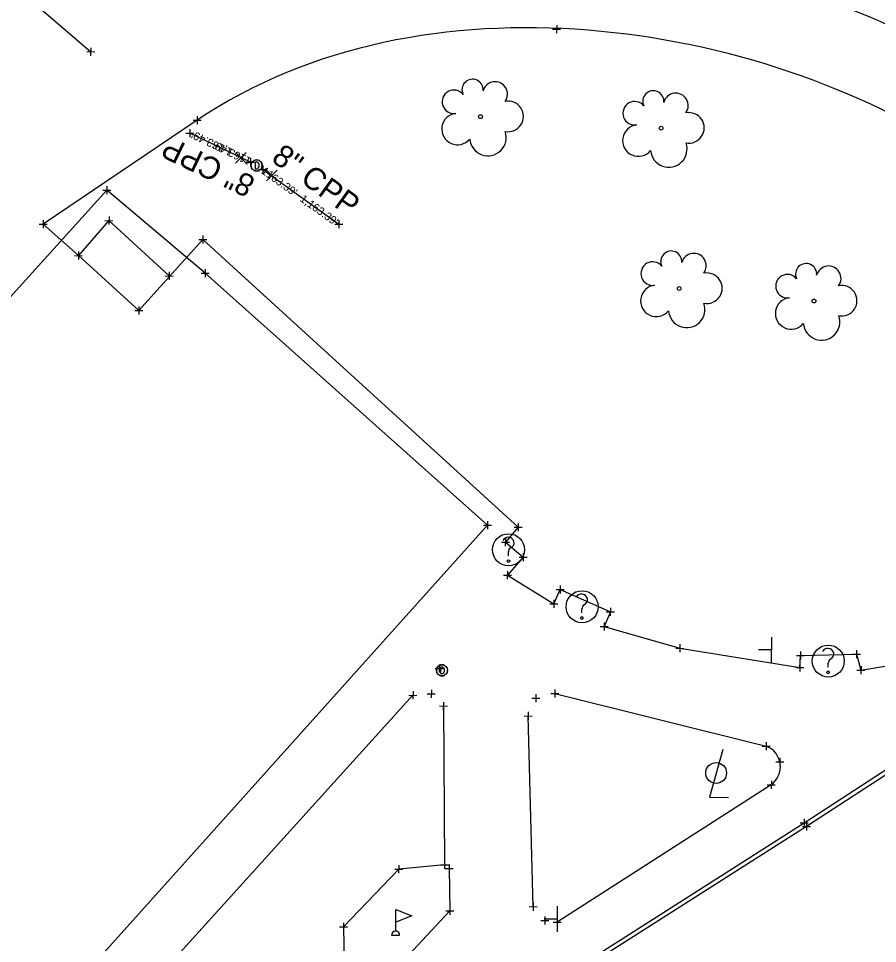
# Model space of a CAD drawing. Extents: x 142461 to 147261, y 511126 to 514697.
# Drawn here: x 145405.1 to 145512.4, y 513850.3 to 513965.9 of the extents above; entities that cross this region are included whole.
import ezdxf

# ---------------------------------------------------------------- set-up
doc = ezdxf.new("R2010")
doc.units = 0
for name, color, linetype in [('BD_X_Building', 7, 'Continuous'), ('DR_X_Cells', 7, 'Continuous'), ('DR_X_Elev_Flow', 7, 'Continuous'), ('DR_X_Storm_Sewer', 7, 'Continuous'), ('DR_X_Text', 7, 'Continuous'), ('GK_Drainage_Nodes', 7, 'Continuous'), ('LT_X_Poles', 7, 'Continuous'), ('PV_X_Curb', 7, 'Continuous'), ('PV_X_EOP', 7, 'Continuous'), ('PV_X_Walk', 7, 'Continuous'), ('RD_X_Cells', 7, 'Continuous'), ('RD_X_Misc_Items', 7, 'Continuous'), ('SC_Scratch1', 7, 'Continuous'), ('SN_X_Public', 7, 'Continuous'), ('SV_X_Random_Point', 7, 'Continuous'), ('SV_X_Shot_Marker', 7, 'Continuous'), ('VG_X_Cells', 7, 'Continuous')]:
    doc.layers.add(name, color=color, linetype=linetype)

msp = doc.modelspace()

# ---------------------------------------------------------------- linework, layer by layer
at = {"layer": 'BD_X_Building'}
msp.add_lwpolyline([(145428.41, 513934.11), (145416.13, 513944.48), (145358.84, 513881.1), (145404.83, 513837.03), (145463.67, 513902.61)], close=True, dxfattribs=at)
at = {"layer": 'DR_X_Cells'}
for points in [[(145434.92, 513947.97), (145434.64, 513947.97), (145434.64, 513947.17), (145434.92, 513947.17)], [(145458.07, 513884.88), (145457.79, 513884.88), (145457.79, 513884.08), (145458.07, 513884.08)]]:
    msp.add_lwpolyline(points, dxfattribs=at)
for centre, radius, start, end in [((145434.82, 513947.57), 0.7, 150.0184, 209.9816), ((145434.82, 513947.57), 0.7, 60.0184, 120.0157), ((145434.67, 513947.57), 0.474, 302.5148, 57.4852), ((145434.82, 513947.57), 0.7, 330.0184, 29.9816), ((145434.82, 513947.57), 0.7, 239.9843, 299.9816), ((145457.97, 513884.48), 0.7, 60.0184, 120.0157), ((145457.97, 513884.48), 0.7, 150.0184, 209.9816), ((145457.97, 513884.48), 0.7, 239.9843, 299.9816), ((145457.82, 513884.47), 0.474, 302.5148, 57.4852), ((145457.97, 513884.48), 0.7, 330.0184, 29.9816)]:
    msp.add_arc(centre, radius, start, end, dxfattribs=at)
at = {"layer": 'DR_X_Elev_Flow'}
for p, q in [((145426.49, 513952.12), (145426.49, 513951.12)), ((145425.99, 513951.62), (145426.99, 513951.62)), ((145426.49, 513951.62), (145426.49, 513951.62)), ((145434.05, 513948.49), (145434.05, 513947.49)), ((145433.55, 513947.99), (145434.55, 513947.99)), ((145434.05, 513947.99), (145434.05, 513947.99)), ((145435.61, 513947.58), (145435.61, 513946.58)), ((145435.11, 513947.08), (145436.11, 513947.08)), ((145435.61, 513947.08), (145435.61, 513947.08)), ((145445.11, 513940.72), (145445.11, 513939.72)), ((145444.61, 513940.22), (145445.61, 513940.22)), ((145445.11, 513940.22), (145445.11, 513940.22))]:
    msp.add_line(p, q, dxfattribs=at)
at = {"layer": 'DR_X_Storm_Sewer'}
for p, q in [((145434.05, 513947.99), (145426.49, 513951.62)), ((145435.61, 513947.08), (145445.11, 513940.22))]:
    msp.add_line(p, q, dxfattribs=at)
at = {"layer": 'GK_Drainage_Nodes'}
for p, q in [((145434.82, 513947.57), (145434.82, 513947.57)), ((145434.82, 513947.57), (145434.82, 513947.57)), ((145434.82, 513947.57), (145434.82, 513947.57)), ((145434.82, 513947.57), (145434.82, 513947.57)), ((145434.82, 513947.57), (145434.82, 513947.57)), ((145457.97, 513884.48), (145457.97, 513884.48)), ((145457.97, 513884.48), (145457.97, 513884.48)), ((145457.97, 513884.48), (145457.97, 513884.48)), ((145457.97, 513884.48), (145457.97, 513884.48)), ((145457.97, 513884.48), (145457.97, 513884.48))]:
    msp.add_line(p, q, dxfattribs=at)
for centre in [(145434.82, 513947.57), (145457.97, 513884.48)]:
    msp.add_circle(centre, 0.7, dxfattribs=at)
at = {"layer": 'LT_X_Poles'}
msp.add_lwpolyline([(145493.03, 513874.59), (145491.4, 513868.62), (145493.76, 513868.6)], dxfattribs=at)
msp.add_circle((145492.21, 513871.65), 1.3, dxfattribs=at)
at = {"layer": 'PV_X_Curb'}
for p, q in [((145424.5, 513848.36), (145454.35, 513881.36)), ((145458.15, 513880.02), (145458.31, 513860.17)), ((145452.57, 513859.63), (145445.66, 513852.42)), ((145458.31, 513860.17), (145452.57, 513859.63)), ((145445.66, 513852.42), (145445.76, 513846.48))]:
    msp.add_line(p, q, dxfattribs=at)
msp.add_lwpolyline([(145227.69, 513660.65), (145214.65, 513681.65), (145226.59, 513689.4), (145227.71, 513690.22), (145253.7, 513706.45), (145254.76, 513707.01), (145306.51, 513740.01), (145357, 513772.11), (145410.28, 513806.15), (145439.46, 513824.75), (145448.27, 513830.42), (145452.54, 513833.13), (145456.82, 513835.85), (145503.2, 513865.44), (145542.33, 513890.92), (145551.43, 513885.04), (145559.02, 513886.59), (145559.54, 513886.77)], dxfattribs=at)
at = {"layer": 'PV_X_EOP'}
for p, q in [((145542.33, 513890.27), (145503.5, 513864.97)), ((145503.5, 513864.97), (145457.13, 513835.46))]:
    msp.add_line(p, q, dxfattribs=at)
at = {"layer": 'PV_X_Walk'}
for p, q in [((145398.1, 513975.57), (145414.11, 513961.79)), ((145427.4, 513953.22), (145408.17, 513940.23)), ((145408.17, 513940.23), (145412.6, 513936.31)), ((145420.13, 513929.45), (145428.12, 513938.33)), ((145428.12, 513938.33), (145467.49, 513902.37)), ((145412.6, 513936.31), (145420.13, 513929.45)), ((145467.49, 513902.37), (145465.89, 513900.48)), ((145465.89, 513900.48), (145468.11, 513898.61)), ((145468.11, 513898.61), (145466.14, 513896.39)), ((145466.14, 513896.39), (145471.96, 513892.78)), ((145471.96, 513892.78), (145472.74, 513894.6)), ((145472.74, 513894.6), (145479, 513891.81)), ((145479, 513891.81), (145478.23, 513889.97)), ((145478.23, 513889.97), (145487.69, 513887.23)), ((145487.69, 513887.23), (145502.68, 513884.84)), ((145502.68, 513884.84), (145502.75, 513886.35)), ((145502.75, 513886.35), (145509.73, 513886.52)), ((145509.73, 513886.52), (145510.3, 513884.49)), ((145510.3, 513884.49), (145522.24, 513886.57)), ((145472.08, 513881.59), (145498.47, 513875.01)), ((145469.36, 513854.94), (145468.73, 513878.78)), ((145499.1, 513870.17), (145472.36, 513853.02))]:
    msp.add_line(p, q, dxfattribs=at)
for points in [[(145423.92, 513933.76), (145416.38, 513940.68), (145412.6, 513936.31)], [(145458.86, 513859.71), (145458.95, 513854.42), (145451.51, 513846.41), (145446.23, 513846.05)]]:
    msp.add_lwpolyline(points, dxfattribs=at)
msp.add_arc((145497.45, 513872.42), 2.79, 306.3448, 68.5669, dxfattribs=at)
for points in [[(145472.53, 513974.48), (145484.74, 513974.18), (145509.54, 513969.49), (145545.43, 513947.45), (145561.22, 513919.51), (145569.48, 513904.18), (145570.81, 513901.55)], [(145560.96, 513887.28), (145560.21, 513895.09), (145555.29, 513916.67), (145527.12, 513951.5), (145476.58, 513968.91), (145441.52, 513962.76), (145427.4, 513953.22)]]:
    msp.add_open_spline(points, degree=3, dxfattribs=at)
at = {"layer": 'RD_X_Cells'}
for p, q in [((145452.2, 513851.9), (145452.23, 513854.6)), ((145454.22, 513853.78), (145452.21, 513853)), ((145452.23, 513854.6), (145454.22, 513853.78)), ((145452.21, 513853), (145452.21, 513853)), ((145451.69, 513851.4), (145452.69, 513851.39))]:
    msp.add_line(p, q, dxfattribs=at)
msp.add_arc((145452.19, 513851.4), 0.5, 359.4086, 179.4086, dxfattribs=at)
at = {"layer": 'RD_X_Misc_Items'}
for p, q in [((145466.28, 513898.8), (145466.29, 513899.27)), ((145475.46, 513891.68), (145475.46, 513892.15)), ((145506.22, 513884.89), (145506.22, 513885.36))]:
    msp.add_line(p, q, dxfattribs=at)
for centre, radius in [((145466.29, 513899.55), 2), ((145466.28, 513898.14), 0.17), ((145475.47, 513892.43), 2), ((145475.45, 513891.02), 0.17), ((145506.22, 513885.64), 2), ((145506.21, 513884.23), 0.17)]:
    msp.add_circle(centre, radius, dxfattribs=at)
for centre, radius, start, end in [((145466.23, 513900.36), 0.754, 87.7326, 151.9471), ((145466.29, 513900.43), 0.688, 291.3416, 91.867), ((145466.87, 513899.31), 0.587, 124.8704, 183.4915), ((145475.41, 513893.25), 0.754, 87.7326, 151.9471), ((145475.46, 513893.31), 0.688, 291.3416, 91.867), ((145476.05, 513892.19), 0.587, 124.8704, 183.4915), ((145506.17, 513886.46), 0.754, 87.7326, 151.9471), ((145506.22, 513886.52), 0.688, 291.3416, 91.867), ((145506.81, 513885.4), 0.587, 124.8704, 183.4915)]:
    msp.add_arc(centre, radius, start, end, dxfattribs=at)
at = {"layer": 'SN_X_Public'}
for p, q in [((145499.13, 513888.63), (145499.1, 513885.43)), ((145499.12, 513887.03), (145497.52, 513887.04)), ((145499.12, 513887.03), (145499.12, 513887.03)), ((145472.35, 513855), (145472.35, 513851.8)), ((145472.35, 513853.4), (145470.75, 513853.4)), ((145472.34, 513853.4), (145472.34, 513853.4))]:
    msp.add_line(p, q, dxfattribs=at)
at = {"layer": 'SV_X_Random_Point'}
for p, q in [((145432.19, 513947.87), (145433.54, 513949.2)), ((145432.21, 513949.21), (145433.53, 513947.86)), ((145436.07, 513945.65), (145437.41, 513946.97)), ((145436.08, 513946.99), (145437.4, 513945.64))]:
    msp.add_line(p, q, dxfattribs=at)
at = {"layer": 'SV_X_Shot_Marker'}
for p, q in [((145472.3, 513965.12), (145472.29, 513964.12)), ((145471.79, 513964.62), (145472.79, 513964.61)), ((145472.29, 513964.62), (145472.29, 513964.62)), ((145413.61, 513961.8), (145414.61, 513961.79)), ((145414.11, 513962.29), (145414.1, 513961.29)), ((145414.11, 513961.79), (145414.11, 513961.79)), ((145426.9, 513953.23), (145427.9, 513953.22)), ((145427.4, 513953.72), (145427.39, 513952.72)), ((145427.4, 513953.22), (145427.4, 513953.22)), ((145415.63, 513944.48), (145416.63, 513944.48)), ((145416.13, 513944.98), (145416.13, 513943.98)), ((145416.13, 513944.48), (145416.13, 513944.48)), ((145408.17, 513940.73), (145408.16, 513939.73)), ((145415.88, 513940.68), (145416.88, 513940.67)), ((145416.39, 513941.18), (145416.38, 513940.18)), ((145416.38, 513940.68), (145416.38, 513940.68)), ((145407.67, 513940.23), (145408.67, 513940.22)), ((145408.17, 513940.23), (145408.17, 513940.23)), ((145427.62, 513938.33), (145428.62, 513938.32)), ((145428.12, 513938.83), (145428.11, 513937.83)), ((145428.12, 513938.33), (145428.12, 513938.33)), ((145412.1, 513936.31), (145413.1, 513936.3)), ((145412.6, 513936.81), (145412.59, 513935.81)), ((145412.6, 513936.31), (145412.6, 513936.31)), ((145428.41, 513934.61), (145428.41, 513933.61)), ((145423.42, 513933.76), (145424.42, 513933.75)), ((145423.92, 513934.26), (145423.91, 513933.26)), ((145423.92, 513933.76), (145423.92, 513933.76)), ((145427.91, 513934.11), (145428.91, 513934.11)), ((145428.41, 513934.11), (145428.41, 513934.11)), ((145419.63, 513929.46), (145420.63, 513929.45)), ((145420.13, 513929.95), (145420.12, 513928.95)), ((145420.13, 513929.45), (145420.13, 513929.45)), ((145463.17, 513902.61), (145464.17, 513902.61)), ((145463.67, 513903.11), (145463.67, 513902.11)), ((145463.67, 513902.61), (145463.67, 513902.61)), ((145466.99, 513902.37), (145467.99, 513902.36)), ((145467.49, 513902.87), (145467.48, 513901.87)), ((145467.49, 513902.37), (145467.49, 513902.37)), ((145465.39, 513900.49), (145466.39, 513900.48)), ((145465.89, 513900.98), (145465.88, 513899.98)), ((145465.89, 513900.48), (145465.89, 513900.48)), ((145468.11, 513899.11), (145468.1, 513898.11)), ((145467.61, 513898.62), (145468.61, 513898.61)), ((145468.11, 513898.61), (145468.11, 513898.61)), ((145466.14, 513896.89), (145466.13, 513895.89)), ((145465.64, 513896.39), (145466.64, 513896.38)), ((145466.14, 513896.39), (145466.14, 513896.39)), ((145472.24, 513894.6), (145473.24, 513894.59)), ((145472.74, 513895.1), (145472.73, 513894.1)), ((145472.74, 513894.6), (145472.74, 513894.6)), ((145471.96, 513893.28), (145471.95, 513892.28)), ((145471.46, 513892.78), (145472.46, 513892.77)), ((145471.96, 513892.78), (145471.96, 513892.78)), ((145479, 513892.31), (145478.99, 513891.31)), ((145478.5, 513891.81), (145479.5, 513891.8)), ((145479, 513891.81), (145479, 513891.81)), ((145477.73, 513889.97), (145478.73, 513889.96)), ((145478.24, 513890.47), (145478.23, 513889.47)), ((145478.23, 513889.97), (145478.23, 513889.97)), ((145487.19, 513887.24), (145488.19, 513887.22)), ((145487.69, 513887.73), (145487.68, 513886.73)), ((145487.69, 513887.23), (145487.69, 513887.23)), ((145502.25, 513886.35), (145503.25, 513886.34)), ((145502.76, 513886.85), (145502.75, 513885.85)), ((145502.75, 513886.35), (145502.75, 513886.35)), ((145509.23, 513886.52), (145510.23, 513886.51)), ((145509.74, 513887.02), (145509.73, 513886.02)), ((145509.73, 513886.52), (145509.73, 513886.52)), ((145457.62, 513885.23), (145457.62, 513884.23)), ((145502.68, 513885.34), (145502.67, 513884.34)), ((145510.31, 513884.99), (145510.3, 513883.99)), ((145457.12, 513884.73), (145458.12, 513884.73)), ((145457.62, 513884.73), (145457.62, 513884.73)), ((145502.18, 513884.85), (145503.18, 513884.84)), ((145502.68, 513884.84), (145502.68, 513884.84)), ((145509.8, 513884.5), (145510.8, 513884.49)), ((145510.3, 513884.49), (145510.3, 513884.49)), ((145454.36, 513881.86), (145454.35, 513880.86)), ((145456.14, 513881.56), (145457.14, 513881.55)), ((145456.65, 513882.06), (145456.64, 513881.06)), ((145456.64, 513881.56), (145456.64, 513881.56)), ((145469.7, 513881.51), (145469.69, 513880.51)), ((145471.58, 513881.6), (145472.58, 513881.59)), ((145472.08, 513882.09), (145472.07, 513881.09)), ((145472.08, 513881.59), (145472.08, 513881.59)), ((145453.85, 513881.36), (145454.85, 513881.35)), ((145454.35, 513881.36), (145454.35, 513881.36)), ((145458.16, 513880.52), (145458.14, 513879.52)), ((145469.2, 513881.02), (145470.2, 513881.01)), ((145469.7, 513881.01), (145469.7, 513881.01)), ((145457.65, 513880.03), (145458.65, 513880.02)), ((145458.15, 513880.02), (145458.15, 513880.02)), ((145468.73, 513879.28), (145468.72, 513878.28)), ((145468.23, 513878.78), (145469.23, 513878.77)), ((145468.73, 513878.78), (145468.73, 513878.78)), ((145497.97, 513875.02), (145498.97, 513875.01)), ((145498.47, 513875.51), (145498.46, 513874.51)), ((145498.47, 513875.01), (145498.47, 513875.01)), ((145500.17, 513873.53), (145500.16, 513872.53)), ((145499.67, 513873.04), (145500.67, 513873.03)), ((145500.17, 513873.03), (145500.17, 513873.03)), ((145498.6, 513870.17), (145499.6, 513870.16)), ((145499.11, 513870.67), (145499.1, 513869.67)), ((145499.1, 513870.17), (145499.1, 513870.17)), ((145502.7, 513865.44), (145503.7, 513865.43)), ((145503.2, 513865.94), (145503.19, 513864.94)), ((145503.2, 513865.44), (145503.2, 513865.44)), ((145503.51, 513865.47), (145503.5, 513864.47)), ((145503, 513864.97), (145504, 513864.96)), ((145503.5, 513864.97), (145503.5, 513864.97)), ((145458.31, 513860.67), (145458.3, 513859.67)), ((145452.07, 513859.64), (145453.07, 513859.63)), ((145452.57, 513860.13), (145452.56, 513859.13)), ((145452.57, 513859.63), (145452.57, 513859.63)), ((145457.81, 513860.17), (145458.81, 513860.16)), ((145458.31, 513860.17), (145458.31, 513860.17)), ((145458.36, 513859.72), (145459.36, 513859.7)), ((145458.87, 513860.21), (145458.86, 513859.21)), ((145458.86, 513859.71), (145458.86, 513859.71)), ((145458.95, 513854.92), (145458.94, 513853.92)), ((145468.86, 513854.95), (145469.86, 513854.94)), ((145469.36, 513855.44), (145469.35, 513854.44)), ((145469.36, 513854.94), (145469.36, 513854.94)), ((145458.45, 513854.42), (145459.45, 513854.41)), ((145458.95, 513854.42), (145458.95, 513854.42)), ((145470.81, 513853.72), (145470.8, 513852.72)), ((145445.67, 513852.92), (145445.66, 513851.92)), ((145470.31, 513853.23), (145471.31, 513853.22)), ((145470.81, 513853.22), (145470.81, 513853.22)), ((145471.86, 513853.02), (145472.86, 513853.01)), ((145472.37, 513853.52), (145472.36, 513852.52)), ((145472.36, 513853.02), (145472.36, 513853.02)), ((145445.16, 513852.43), (145446.16, 513852.42)), ((145445.66, 513852.42), (145445.66, 513852.42))]:
    msp.add_line(p, q, dxfattribs=at)
at = {"layer": 'VG_X_Cells'}
for centre in [(145462.78, 513953.67), (145485.35, 513952.23), (145487.6, 513932.2), (145504.43, 513930.63)]:
    msp.add_circle(centre, 0.24, dxfattribs=at)
for centre, radius, start, end in [((145461.79, 513957.03), 1.32, 354.0047, 205.9741), ((145464.6, 513956.49), 1.55, 323.83, 165.0376), ((145459.47, 513955.53), 1.47, 39.0625, 279.5412), ((145484.37, 513955.6), 1.32, 354.0047, 205.9741), ((145487.18, 513955.06), 1.55, 323.83, 165.0376), ((145466.24, 513953.7), 1.91, 259.1453, 101.4596), ((145482.04, 513954.1), 1.47, 39.0625, 279.5412), ((145459.92, 513952.12), 1.97, 96.1722, 320.5737), ((145488.81, 513952.27), 1.91, 259.1453, 101.4596), ((145482.5, 513950.68), 1.97, 96.1722, 320.5737), ((145463.72, 513951.06), 2.28, 184.9476, 19.4572), ((145486.3, 513949.63), 2.28, 184.9476, 19.4572), ((145486.61, 513935.57), 1.32, 354.0047, 205.9741), ((145489.42, 513935.03), 1.55, 323.83, 165.0376), ((145484.29, 513934.06), 1.47, 39.0625, 279.5412), ((145503.45, 513934), 1.32, 354.0047, 205.9741), ((145506.26, 513933.46), 1.55, 323.83, 165.0376), ((145491.06, 513932.23), 1.91, 259.1453, 101.4596), ((145501.12, 513932.49), 1.47, 39.0625, 279.5412), ((145484.74, 513930.65), 1.97, 96.1722, 320.5737), ((145507.89, 513930.67), 1.91, 259.1453, 101.4596), ((145488.54, 513929.59), 2.28, 184.9476, 19.4572), ((145501.58, 513929.08), 1.97, 96.1722, 320.5737), ((145505.38, 513928.02), 2.28, 184.9476, 19.4572)]:
    msp.add_arc(centre, radius, start, end, dxfattribs=at)

# ---------------------------------------------------------------- texts
at = {"layer": 'DR_X_Text'}
for rotation, p in [(154.3044, (145434.84, 513946.01)), (324.1678, (145436.53, 513948.18))]:
    msp.add_text('8" CPP', height=2.8, rotation=rotation, dxfattribs=at).set_placement(p)
at = {"layer": 'SC_Scratch1'}
for s, rotation, p in [("1,163.49'", 154.3044, (145431.92, 513949.57)), ("1163.49'", 154.3044, (145434.27, 513948.44)), ("1163.39'", 324.1678, (145435.32, 513946.67)), ("1,163.39'", 324.1678, (145440.14, 513943.2))]:
    msp.add_text(s, height=1, rotation=rotation, dxfattribs=at).set_placement(p)

doc.saveas('drawing.dxf')
